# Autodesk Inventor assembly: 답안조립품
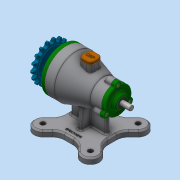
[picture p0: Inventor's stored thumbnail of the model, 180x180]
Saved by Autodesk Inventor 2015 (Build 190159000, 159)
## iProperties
Created: 2018-03
Part Number: 답안조립품
Document SubType Name: Assembly
Designer: SCD-A03
Author: SCD-A03
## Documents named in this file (15)
- C:\Users\SCD-A03\Desktop\Documents\480307V1017\답안조립품.iam
- C:\Users\SCD-A03\Desktop\Documents\480307V1017\뒤커버.ipt
- C:\Users\SCD-A03\Desktop\Documents\480307V1017\마개.ipt
- C:\Users\SCD-A03\Desktop\Documents\480307V1017\베어링-6200.ipt
- C:\Users\SCD-A03\Desktop\Documents\480307V1017\베어링-6203.ipt
- C:\Users\SCD-A03\Desktop\Documents\480307V1017\본체.ipt
- C:\Users\SCD-A03\Desktop\Documents\480307V1017\볼트 M4 x 12.ipt
- 볼트 M4 x 12.ipt
- C:\Users\SCD-A03\Desktop\Documents\480307V1017\스프로킷.ipt
- C:\Users\SCD-A03\Desktop\Documents\480307V1017\앞커버.ipt
- C:\Users\SCD-A03\Desktop\Documents\480307V1017\오일 실 10 20 7.ipt
- C:\Users\SCD-A03\Desktop\Documents\480307V1017\오일 실 17 30 8.ipt
- C:\Users\SCD-A03\Desktop\Documents\480307V1017\축.ipt
- C:\Users\SCD-A03\Desktop\Documents\480307V1017\키 5 x 5.ipt
- 키 5 x 5.ipt
